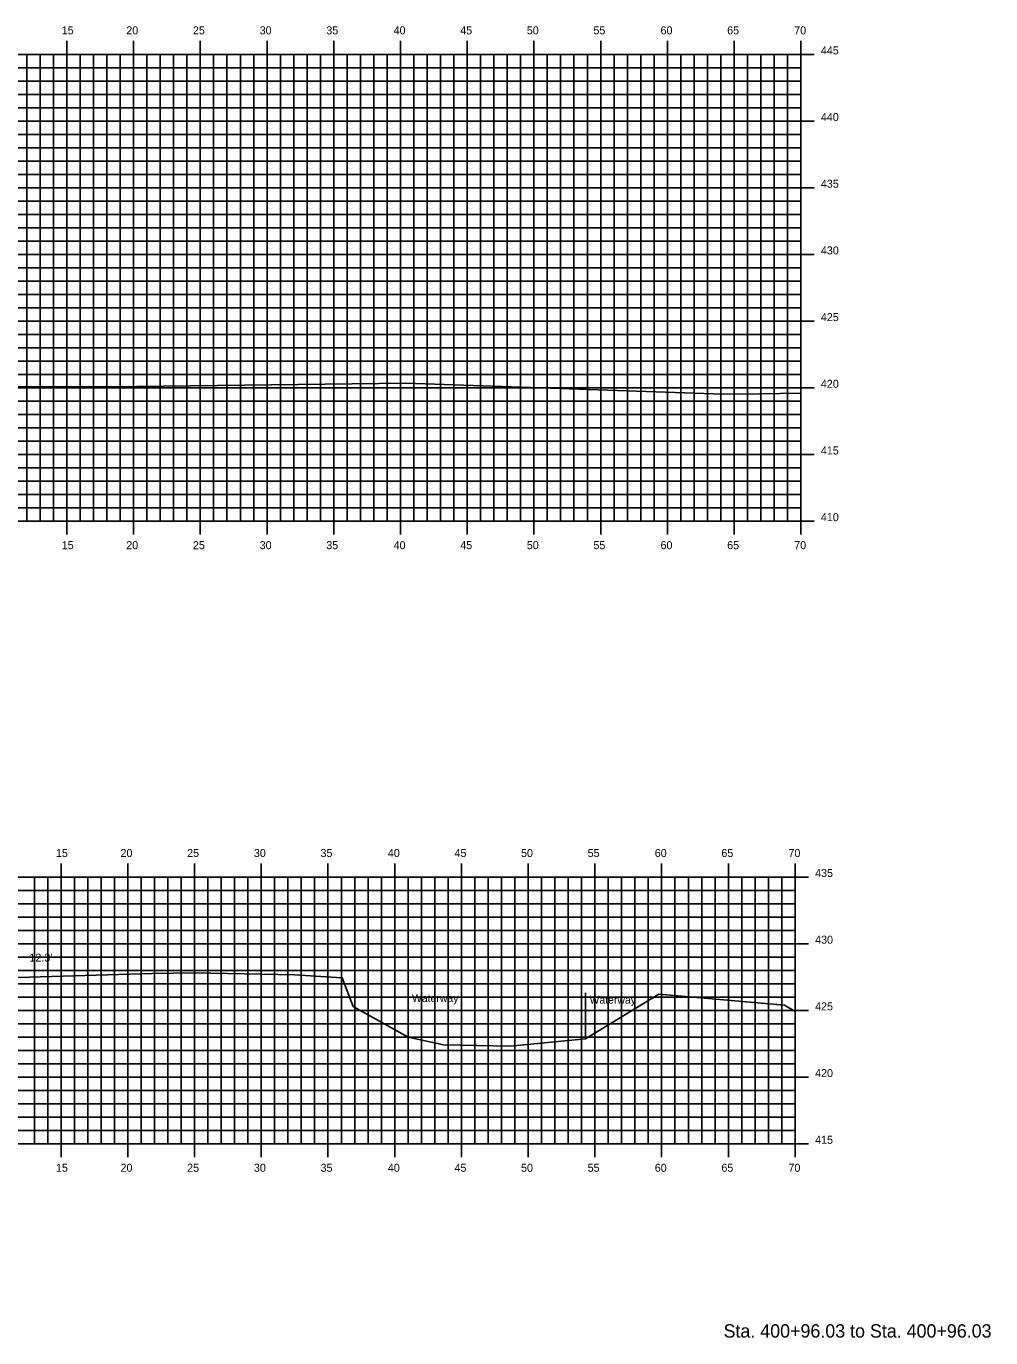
# Model space of a CAD drawing. Extents: x -161 to 764, y 111 to 210.
# Drawn here: x 691.6 to 763.9, y 111.2 to 209.6 of the extents above; entities that cross this region are included whole.
import ezdxf

# ---------------------------------------------------------------- set-up
doc = ezdxf.new("R2010")
doc.units = 0
for name, color, linetype in [('D_Text_Standard', 7, 'Continuous'), ('H_V ANNOTATION', 7, 'Continuous'), ('MAJOR', 7, 'Continuous'), ('MINOR', 7, 'Continuous'), ('S_Drainage_Waterway', 7, 'Continuous'), ('S_Roadway_Centerline', 7, 'Continuous')]:
    doc.layers.add(name, color=color, linetype=linetype)

msp = doc.modelspace()

# ---------------------------------------------------------------- linework, layer by layer
at = {"layer": 'MAJOR'}
for p, q in [((694.651, 208.447), (694.651, 207.445)), ((699.651, 208.447), (699.651, 207.445)), ((704.651, 208.447), (704.651, 207.445)), ((709.651, 208.447), (709.651, 207.445)), ((714.651, 208.447), (714.651, 207.445)), ((719.651, 208.447), (719.651, 207.445)), ((724.651, 208.447), (724.651, 207.445)), ((729.651, 208.447), (729.651, 207.445)), ((734.651, 208.447), (734.651, 207.445)), ((739.651, 208.447), (739.651, 207.445)), ((744.651, 208.447), (744.651, 207.445)), ((749.651, 208.447), (749.651, 207.445)), ((609.651, 207.445), (749.651, 207.445)), ((609.651, 207.445), (749.651, 207.445)), ((694.651, 172.445), (694.651, 207.445)), ((699.651, 172.445), (699.651, 207.445)), ((704.651, 172.445), (704.651, 207.445)), ((709.651, 172.445), (709.651, 207.445)), ((714.651, 172.445), (714.651, 207.445)), ((719.651, 172.445), (719.651, 207.445)), ((724.651, 172.445), (724.651, 207.445)), ((729.651, 172.445), (729.651, 207.445)), ((734.651, 172.445), (734.651, 207.445)), ((739.651, 172.445), (739.651, 207.445)), ((744.651, 172.445), (744.651, 207.445)), ((750.653, 207.445), (748.649, 207.445)), ((749.651, 172.445), (749.651, 207.445)), ((749.651, 172.445), (749.651, 207.445)), ((609.651, 202.445), (749.651, 202.445)), ((750.653, 202.445), (748.649, 202.445)), ((609.651, 197.445), (749.651, 197.445)), ((750.653, 197.445), (748.649, 197.445)), ((609.651, 192.445), (749.651, 192.445)), ((750.653, 192.445), (748.649, 192.445)), ((609.651, 187.445), (749.651, 187.445)), ((750.653, 187.445), (748.649, 187.445)), ((609.651, 182.445), (749.651, 182.445)), ((750.653, 182.445), (748.649, 182.445)), ((609.651, 177.445), (749.651, 177.445)), ((750.653, 177.445), (748.649, 177.445)), ((609.651, 172.445), (749.651, 172.445)), ((609.651, 172.445), (749.651, 172.445)), ((694.651, 171.443), (694.651, 172.445)), ((699.651, 171.443), (699.651, 172.445)), ((704.651, 171.443), (704.651, 172.445)), ((709.651, 171.443), (709.651, 172.445)), ((714.651, 171.443), (714.651, 172.445)), ((719.651, 171.443), (719.651, 172.445)), ((724.651, 171.443), (724.651, 172.445)), ((729.651, 171.443), (729.651, 172.445)), ((734.651, 171.443), (734.651, 172.445)), ((739.651, 171.443), (739.651, 172.445)), ((744.651, 171.443), (744.651, 172.445)), ((750.653, 172.445), (748.649, 172.445)), ((749.651, 171.443), (749.651, 172.445)), ((694.219, 146.766), (694.219, 145.764)), ((699.219, 146.766), (699.219, 145.764)), ((704.219, 146.766), (704.219, 145.764)), ((709.219, 146.766), (709.219, 145.764)), ((714.219, 146.766), (714.219, 145.764)), ((719.219, 146.766), (719.219, 145.764)), ((724.219, 146.766), (724.219, 145.764)), ((729.219, 146.766), (729.219, 145.764)), ((734.219, 146.766), (734.219, 145.764)), ((739.219, 146.766), (739.219, 145.764)), ((744.219, 146.766), (744.219, 145.764)), ((749.219, 146.766), (749.219, 145.764)), ((609.219, 145.764), (749.219, 145.764)), ((609.219, 145.764), (749.219, 145.764)), ((694.219, 125.764), (694.219, 145.764)), ((699.219, 125.764), (699.219, 145.764)), ((704.219, 125.764), (704.219, 145.764)), ((709.219, 125.764), (709.219, 145.764)), ((714.219, 125.764), (714.219, 145.764)), ((719.219, 125.764), (719.219, 145.764)), ((724.219, 125.764), (724.219, 145.764)), ((729.219, 125.764), (729.219, 145.764)), ((734.219, 125.764), (734.219, 145.764)), ((739.219, 125.764), (739.219, 145.764)), ((744.219, 125.764), (744.219, 145.764)), ((750.221, 145.764), (748.217, 145.764)), ((749.219, 125.764), (749.219, 145.764)), ((749.219, 125.764), (749.219, 145.764)), ((609.219, 140.764), (749.219, 140.764)), ((750.221, 140.764), (748.217, 140.764)), ((609.219, 135.764), (749.219, 135.764)), ((750.221, 135.764), (748.217, 135.764)), ((609.219, 130.764), (749.219, 130.764)), ((750.221, 130.764), (748.217, 130.764)), ((609.219, 125.764), (749.219, 125.764)), ((609.219, 125.764), (749.219, 125.764)), ((694.219, 124.762), (694.219, 125.764)), ((699.219, 124.762), (699.219, 125.764)), ((704.219, 124.762), (704.219, 125.764)), ((709.219, 124.762), (709.219, 125.764)), ((714.219, 124.762), (714.219, 125.764)), ((719.219, 124.762), (719.219, 125.764)), ((724.219, 124.762), (724.219, 125.764)), ((729.219, 124.762), (729.219, 125.764)), ((734.219, 124.762), (734.219, 125.764)), ((739.219, 124.762), (739.219, 125.764)), ((744.219, 124.762), (744.219, 125.764)), ((750.221, 125.764), (748.217, 125.764)), ((749.219, 124.762), (749.219, 125.764))]:
    msp.add_line(p, q, dxfattribs=at)
at = {"layer": 'MINOR'}
for p, q in [((691.651, 172.445), (691.651, 207.445)), ((692.651, 172.445), (692.651, 207.445)), ((693.651, 172.445), (693.651, 207.445)), ((695.651, 172.445), (695.651, 207.445)), ((696.651, 172.445), (696.651, 207.445)), ((697.651, 172.445), (697.651, 207.445)), ((698.651, 172.445), (698.651, 207.445)), ((700.651, 172.445), (700.651, 207.445)), ((701.651, 172.445), (701.651, 207.445)), ((702.651, 172.445), (702.651, 207.445)), ((703.651, 172.445), (703.651, 207.445)), ((705.651, 172.445), (705.651, 207.445)), ((706.651, 172.445), (706.651, 207.445)), ((707.651, 172.445), (707.651, 207.445)), ((708.651, 172.445), (708.651, 207.445)), ((710.651, 172.445), (710.651, 207.445)), ((711.651, 172.445), (711.651, 207.445)), ((712.651, 172.445), (712.651, 207.445)), ((713.651, 172.445), (713.651, 207.445)), ((715.651, 172.445), (715.651, 207.445)), ((716.651, 172.445), (716.651, 207.445)), ((717.651, 172.445), (717.651, 207.445)), ((718.651, 172.445), (718.651, 207.445)), ((720.651, 172.445), (720.651, 207.445)), ((721.651, 172.445), (721.651, 207.445)), ((722.651, 172.445), (722.651, 207.445)), ((723.651, 172.445), (723.651, 207.445)), ((725.651, 172.445), (725.651, 207.445)), ((726.651, 172.445), (726.651, 207.445)), ((727.651, 172.445), (727.651, 207.445)), ((728.651, 172.445), (728.651, 207.445)), ((730.651, 172.445), (730.651, 207.445)), ((731.651, 172.445), (731.651, 207.445)), ((732.651, 172.445), (732.651, 207.445)), ((733.651, 172.445), (733.651, 207.445)), ((735.651, 172.445), (735.651, 207.445)), ((736.651, 172.445), (736.651, 207.445)), ((737.651, 172.445), (737.651, 207.445)), ((738.651, 172.445), (738.651, 207.445)), ((740.651, 172.445), (740.651, 207.445)), ((741.651, 172.445), (741.651, 207.445)), ((742.651, 172.445), (742.651, 207.445)), ((743.651, 172.445), (743.651, 207.445)), ((745.651, 172.445), (745.651, 207.445)), ((746.651, 172.445), (746.651, 207.445)), ((747.651, 172.445), (747.651, 207.445)), ((748.651, 172.445), (748.651, 207.445)), ((609.651, 206.445), (749.651, 206.445)), ((749.651, 206.445), (748.649, 206.445)), ((609.651, 205.445), (749.651, 205.445)), ((749.651, 205.445), (748.649, 205.445)), ((609.651, 204.445), (749.651, 204.445)), ((749.651, 204.445), (748.649, 204.445)), ((609.651, 203.445), (749.651, 203.445)), ((749.651, 203.445), (748.649, 203.445)), ((609.651, 201.445), (749.651, 201.445)), ((749.651, 201.445), (748.649, 201.445)), ((609.651, 200.445), (749.651, 200.445)), ((749.651, 200.445), (748.649, 200.445)), ((609.651, 199.445), (749.651, 199.445)), ((749.651, 199.445), (748.649, 199.445)), ((609.651, 198.445), (749.651, 198.445)), ((749.651, 198.445), (748.649, 198.445)), ((609.651, 196.445), (749.651, 196.445)), ((749.651, 196.445), (748.649, 196.445)), ((609.651, 195.445), (749.651, 195.445)), ((749.651, 195.445), (748.649, 195.445)), ((609.651, 194.445), (749.651, 194.445)), ((749.651, 194.445), (748.649, 194.445)), ((609.651, 193.445), (749.651, 193.445)), ((749.651, 193.445), (748.649, 193.445)), ((609.651, 191.445), (749.651, 191.445)), ((749.651, 191.445), (748.649, 191.445)), ((609.651, 190.445), (749.651, 190.445)), ((749.651, 190.445), (748.649, 190.445)), ((609.651, 189.445), (749.651, 189.445)), ((749.651, 189.445), (748.649, 189.445)), ((609.651, 188.445), (749.651, 188.445)), ((749.651, 188.445), (748.649, 188.445)), ((609.651, 186.445), (749.651, 186.445)), ((749.651, 186.445), (748.649, 186.445)), ((609.651, 185.445), (749.651, 185.445)), ((749.651, 185.445), (748.649, 185.445)), ((609.651, 184.445), (749.651, 184.445)), ((749.651, 184.445), (748.649, 184.445)), ((609.651, 183.445), (749.651, 183.445)), ((749.651, 183.445), (748.649, 183.445)), ((609.651, 181.445), (749.651, 181.445)), ((749.651, 181.445), (748.649, 181.445)), ((609.651, 180.445), (749.651, 180.445)), ((749.651, 180.445), (748.649, 180.445)), ((609.651, 179.445), (749.651, 179.445)), ((749.651, 179.445), (748.649, 179.445)), ((609.651, 178.445), (749.651, 178.445)), ((749.651, 178.445), (748.649, 178.445)), ((609.651, 176.445), (749.651, 176.445)), ((749.651, 176.445), (748.649, 176.445)), ((609.651, 175.445), (749.651, 175.445)), ((749.651, 175.445), (748.649, 175.445)), ((609.651, 174.445), (749.651, 174.445)), ((749.651, 174.445), (748.649, 174.445)), ((609.651, 173.445), (749.651, 173.445)), ((749.651, 173.445), (748.649, 173.445)), ((692.219, 125.764), (692.219, 145.764)), ((693.219, 125.764), (693.219, 145.764)), ((695.219, 125.764), (695.219, 145.764)), ((696.219, 125.764), (696.219, 145.764)), ((697.219, 125.764), (697.219, 145.764)), ((698.219, 125.764), (698.219, 145.764)), ((700.219, 125.764), (700.219, 145.764)), ((701.219, 125.764), (701.219, 145.764)), ((702.219, 125.764), (702.219, 145.764)), ((703.219, 125.764), (703.219, 145.764)), ((705.219, 125.764), (705.219, 145.764)), ((706.219, 125.764), (706.219, 145.764)), ((707.219, 125.764), (707.219, 145.764)), ((708.219, 125.764), (708.219, 145.764)), ((710.219, 125.764), (710.219, 145.764)), ((711.219, 125.764), (711.219, 145.764)), ((712.219, 125.764), (712.219, 145.764)), ((713.219, 125.764), (713.219, 145.764)), ((715.219, 125.764), (715.219, 145.764)), ((716.219, 125.764), (716.219, 145.764)), ((717.219, 125.764), (717.219, 145.764)), ((718.219, 125.764), (718.219, 145.764)), ((720.219, 125.764), (720.219, 145.764)), ((721.219, 125.764), (721.219, 145.764)), ((722.219, 125.764), (722.219, 145.764)), ((723.219, 125.764), (723.219, 145.764)), ((725.219, 125.764), (725.219, 145.764)), ((726.219, 125.764), (726.219, 145.764)), ((727.219, 125.764), (727.219, 145.764)), ((728.219, 125.764), (728.219, 145.764)), ((730.219, 125.764), (730.219, 145.764)), ((731.219, 125.764), (731.219, 145.764)), ((732.219, 125.764), (732.219, 145.764)), ((733.219, 125.764), (733.219, 145.764)), ((735.219, 125.764), (735.219, 145.764)), ((736.219, 125.764), (736.219, 145.764)), ((737.219, 125.764), (737.219, 145.764)), ((738.219, 125.764), (738.219, 145.764)), ((740.219, 125.764), (740.219, 145.764)), ((741.219, 125.764), (741.219, 145.764)), ((742.219, 125.764), (742.219, 145.764)), ((743.219, 125.764), (743.219, 145.764)), ((745.219, 125.764), (745.219, 145.764)), ((746.219, 125.764), (746.219, 145.764)), ((747.219, 125.764), (747.219, 145.764)), ((748.219, 125.764), (748.219, 145.764)), ((609.219, 144.764), (749.219, 144.764)), ((749.219, 144.764), (748.217, 144.764)), ((609.219, 143.764), (749.219, 143.764)), ((749.219, 143.764), (748.217, 143.764)), ((609.219, 142.764), (749.219, 142.764)), ((749.219, 142.764), (748.217, 142.764)), ((609.219, 141.764), (749.219, 141.764)), ((749.219, 141.764), (748.217, 141.764)), ((609.219, 139.764), (749.219, 139.764)), ((749.219, 139.764), (748.217, 139.764)), ((609.219, 138.764), (749.219, 138.764)), ((749.219, 138.764), (748.217, 138.764)), ((609.219, 137.764), (749.219, 137.764)), ((749.219, 137.764), (748.217, 137.764)), ((609.219, 136.764), (749.219, 136.764)), ((749.219, 136.764), (748.217, 136.764)), ((609.219, 134.764), (749.219, 134.764)), ((749.219, 134.764), (748.217, 134.764)), ((609.219, 133.764), (749.219, 133.764)), ((749.219, 133.764), (748.217, 133.764)), ((609.219, 132.764), (749.219, 132.764)), ((749.219, 132.764), (748.217, 132.764)), ((609.219, 131.764), (749.219, 131.764)), ((749.219, 131.764), (748.217, 131.764)), ((609.219, 129.764), (749.219, 129.764)), ((749.219, 129.764), (748.217, 129.764)), ((609.219, 128.764), (749.219, 128.764)), ((749.219, 128.764), (748.217, 128.764)), ((609.219, 127.764), (749.219, 127.764)), ((749.219, 127.764), (748.217, 127.764)), ((609.219, 126.764), (749.219, 126.764)), ((749.219, 126.764), (748.217, 126.764))]:
    msp.add_line(p, q, dxfattribs=at)
at = {"layer": 'S_Drainage_Waterway'}
for p, q in [((720.217, 137.2), (720.217, 133.759)), ((733.52, 137.083), (733.52, 133.642))]:
    msp.add_line(p, q, dxfattribs=at)
at = {"layer": 'S_Roadway_Centerline'}
for points in [[(609.651, 200.64), (616.732, 200.65), (616.804, 200.646), (616.912, 200.65), (620.887, 184.913), (621.382, 182.041), (633.421, 182.08), (634.076, 182.15), (635.455, 182.164), (649.077, 182.919), (653.611, 183.066), (657.968, 182.967), (679.594, 182.505), (693.81, 182.535), (697.869, 182.505), (720.057, 182.802), (743.82, 181.969), (746.552, 181.996), (749.651, 182.04)], [(685.927, 138.075), (701.051, 138.521), (704.187, 138.576), (711.697, 138.427), (715.284, 138.193), (716.116, 136.053), (720.217, 133.759), (722.88, 133.175), (727.858, 133.074), (733.52, 133.642), (739.001, 136.981), (748.429, 136.165), (749.219, 135.671)]]:
    msp.add_lwpolyline(points, dxfattribs=at)

# ---------------------------------------------------------------- texts
at = {"layer": 'D_Text_Standard'}
msp.add_text("12.3'", height=0.6, dxfattribs=at).set_placement((691.85, 139.421))
at = {"layer": 'H_V ANNOTATION'}
for s, height, p in [('15', 0.6, (694.269, 208.945)), ('20', 0.6, (699.105, 208.945)), ('25', 0.6, (704.097, 208.945)), ('30', 0.6, (709.1, 208.945)), ('35', 0.6, (714.092, 208.945)), ('40', 0.6, (719.137, 208.945)), ('45', 0.6, (724.129, 208.945)), ('50', 0.6, (729.116, 208.945)), ('55', 0.6, (734.108, 208.945)), ('60', 0.6, (739.137, 208.945)), ('65', 0.6, (744.129, 208.945)), ('70', 0.6, (749.153, 208.945)), ('445', 0.6, (751.151, 207.445)), ('440', 0.6, (751.151, 202.445)), ('435', 0.6, (751.151, 197.445)), ('430', 0.6, (751.151, 192.445)), ('425', 0.6, (751.151, 187.445)), ('420', 0.6, (751.151, 182.445)), ('415', 0.6, (751.151, 177.445)), ('410', 0.6, (751.151, 172.445)), ('15', 0.6, (694.269, 170.345)), ('20', 0.6, (699.105, 170.345)), ('25', 0.6, (704.097, 170.345)), ('30', 0.6, (709.1, 170.345)), ('35', 0.6, (714.092, 170.345)), ('40', 0.6, (719.137, 170.345)), ('45', 0.6, (724.129, 170.345)), ('50', 0.6, (729.116, 170.345)), ('55', 0.6, (734.108, 170.345)), ('60', 0.6, (739.137, 170.345)), ('65', 0.6, (744.129, 170.345)), ('70', 0.6, (749.153, 170.345)), ('15', 0.6, (693.836, 147.264)), ('20', 0.6, (698.673, 147.264)), ('25', 0.6, (703.665, 147.264)), ('30', 0.6, (708.668, 147.264)), ('35', 0.6, (713.66, 147.264)), ('40', 0.6, (718.705, 147.264)), ('45', 0.6, (723.697, 147.264)), ('50', 0.6, (728.684, 147.264)), ('55', 0.6, (733.676, 147.264)), ('60', 0.6, (738.705, 147.264)), ('65', 0.6, (743.697, 147.264)), ('70', 0.6, (748.721, 147.264)), ('435', 0.6, (750.719, 145.764)), ('430', 0.6, (750.719, 140.764)), ('425', 0.6, (750.719, 135.764)), ('420', 0.6, (750.719, 130.764)), ('415', 0.6, (750.719, 125.764)), ('15', 0.6, (693.836, 123.664)), ('20', 0.6, (698.673, 123.664)), ('25', 0.6, (703.665, 123.664)), ('30', 0.6, (708.668, 123.664)), ('35', 0.6, (713.66, 123.664)), ('40', 0.6, (718.705, 123.664)), ('45', 0.6, (723.697, 123.664)), ('50', 0.6, (728.684, 123.664)), ('55', 0.6, (733.676, 123.664)), ('60', 0.6, (738.705, 123.664)), ('65', 0.6, (743.697, 123.664)), ('70', 0.6, (748.721, 123.664)), ('Sta. 400+96.03 to Sta. 400+96.03', 1.0002, (743.858, 111.232))]:
    msp.add_text(s, height=height, rotation=360, dxfattribs=at).set_placement(p)
at = {"layer": 'S_Drainage_Waterway'}
for p in [(720.514, 136.388), (733.818, 136.271)]:
    msp.add_text('Waterway', height=0.585, rotation=360, dxfattribs=at).set_placement(p)

doc.saveas('drawing.dxf')
